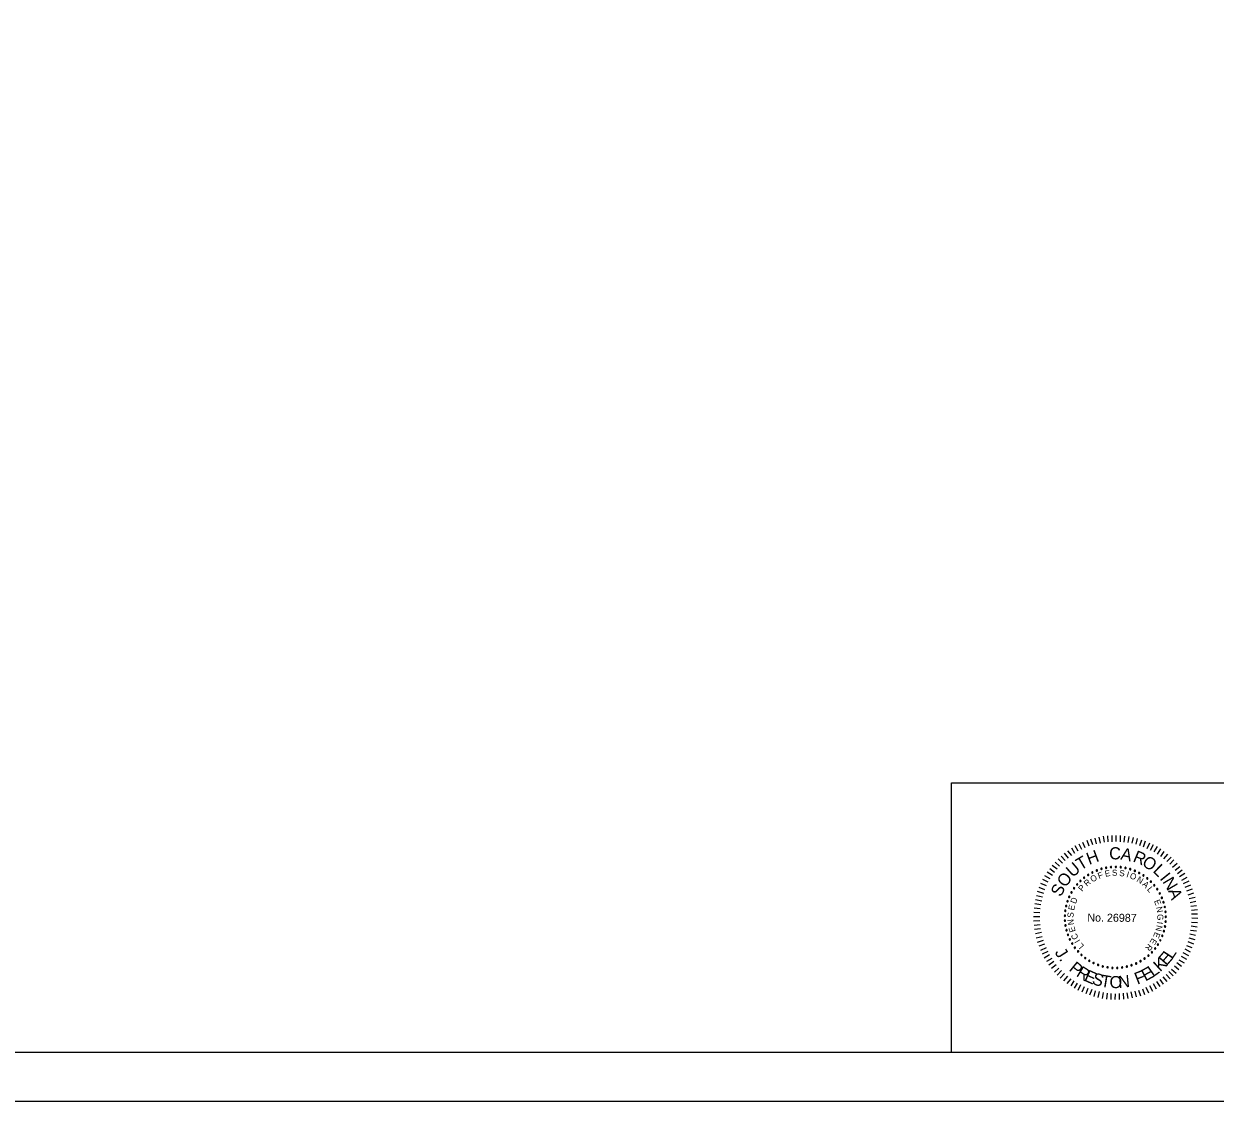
# Model space of a CAD drawing. Extents: x 2799.7 to 2896, y 515.2 to 573.9.
# Drawn here: x 2834.77 to 2867.23, y 515.22 to 544.56 of the extents above; entities that cross this region are included whole.
import ezdxf

# ---------------------------------------------------------------- set-up
doc = ezdxf.new("R2010")
doc.units = 0
for name, color, linetype in [('BR_BORDER LINES', 7, 'Continuous'), ('BR_TEXT', 7, 'Continuous'), ('Level 31', 7, 'Continuous')]:
    doc.layers.add(name, color=color, linetype=linetype)

msp = doc.modelspace()

# ---------------------------------------------------------------- linework, layer by layer
at = {"layer": 'BR_BORDER LINES'}
for p, q in [((2860.05, 523.89), (2874.358, 523.89)), ((2860.05, 516.556), (2860.05, 523.89)), ((2804.582, 516.556), (2894.359, 516.556))]:
    msp.add_line(p, q, dxfattribs=at)
at = {"layer": 'BR_TEXT'}
for p, q in [((2863.694, 522.12), (2863.631, 522.269)), ((2863.798, 522.165), (2863.742, 522.321)), ((2863.903, 522.198), (2863.845, 522.352)), ((2864, 522.225), (2863.964, 522.387)), ((2864.11, 522.251), (2864.072, 522.409)), ((2864.215, 522.271), (2864.191, 522.434)), ((2864.32, 522.282), (2864.31, 522.444)), ((2864.426, 522.288), (2864.427, 522.459)), ((2864.538, 522.293), (2864.539, 522.458)), ((2864.65, 522.286), (2864.656, 522.457)), ((2864.757, 522.278), (2864.77, 522.44)), ((2864.86, 522.266), (2864.889, 522.428)), ((2864.968, 522.244), (2865.006, 522.402)), ((2865.077, 522.216), (2865.12, 522.378)), ((2865.176, 522.188), (2865.234, 522.34)), ((2865.281, 522.152), (2865.339, 522.307)), ((2863.237, 521.84), (2863.13, 521.973)), ((2863.326, 521.908), (2863.222, 522.043)), ((2863.409, 521.964), (2863.328, 522.109)), ((2863.504, 522.027), (2863.422, 522.172)), ((2863.596, 522.075), (2863.526, 522.224)), ((2865.376, 522.106), (2865.451, 522.254)), ((2865.472, 522.059), (2865.556, 522.207)), ((2865.572, 522.01), (2865.658, 522.154)), ((2865.661, 521.946), (2865.751, 522.089)), ((2865.75, 521.888), (2865.847, 522.022)), ((2865.836, 521.818), (2865.945, 521.95)), ((2862.925, 521.536), (2862.793, 521.64)), ((2862.992, 521.62), (2862.876, 521.733)), ((2863.071, 521.701), (2862.953, 521.819)), ((2863.149, 521.774), (2863.038, 521.894)), ((2865.92, 521.751), (2866.036, 521.869)), ((2865.995, 521.677), (2866.111, 521.793)), ((2866.07, 521.594), (2866.197, 521.705)), ((2862.733, 521.272), (2862.59, 521.358)), ((2862.798, 521.37), (2862.654, 521.458)), ((2862.856, 521.447), (2862.724, 521.553)), ((2866.143, 521.509), (2866.267, 521.611)), ((2866.206, 521.419), (2866.337, 521.523)), ((2866.265, 521.341), (2866.405, 521.427)), ((2866.323, 521.242), (2866.466, 521.326)), ((2862.593, 520.98), (2862.438, 521.038)), ((2862.64, 521.083), (2862.487, 521.15)), ((2862.686, 521.181), (2862.536, 521.255)), ((2866.371, 521.15), (2866.525, 521.222)), ((2866.418, 521.051), (2866.57, 521.116)), ((2866.463, 520.948), (2866.614, 521.004)), ((2862.508, 520.665), (2862.342, 520.707)), ((2862.528, 520.777), (2862.365, 520.817)), ((2862.56, 520.873), (2862.396, 520.933)), ((2866.499, 520.84), (2866.652, 520.898)), ((2866.525, 520.744), (2866.686, 520.781)), ((2866.547, 520.631), (2866.708, 520.671)), ((2862.46, 520.354), (2862.288, 520.355)), ((2862.468, 520.459), (2862.303, 520.479)), ((2862.48, 520.569), (2862.318, 520.591)), ((2866.569, 520.535), (2866.727, 520.554)), ((2866.587, 520.425), (2866.749, 520.442)), ((2866.59, 520.32), (2866.751, 520.319)), ((2862.458, 520.13), (2862.286, 520.127)), ((2862.454, 520.244), (2862.287, 520.246)), ((2862.464, 520.027), (2862.299, 520.007)), ((2866.589, 520.096), (2866.749, 520.09)), ((2866.596, 520.21), (2866.759, 520.209)), ((2862.475, 519.917), (2862.312, 519.893)), ((2862.501, 519.811), (2862.334, 519.776)), ((2862.519, 519.699), (2862.356, 519.661)), ((2866.54, 519.778), (2866.7, 519.74)), ((2866.564, 519.883), (2866.722, 519.856)), ((2866.583, 519.993), (2866.746, 519.971)), ((2862.55, 519.6), (2862.385, 519.544)), ((2862.581, 519.497), (2862.425, 519.441)), ((2862.626, 519.398), (2862.472, 519.326)), ((2866.404, 519.367), (2866.555, 519.293)), ((2866.451, 519.465), (2866.601, 519.407)), ((2866.488, 519.568), (2866.641, 519.509)), ((2866.516, 519.666), (2866.676, 519.626)), ((2862.671, 519.302), (2862.519, 519.223)), ((2862.716, 519.203), (2862.571, 519.12)), ((2862.779, 519.104), (2862.634, 519.021)), ((2862.836, 519.026), (2862.702, 518.928)), ((2866.246, 519.075), (2866.385, 518.99)), ((2866.306, 519.173), (2866.448, 519.088)), ((2866.355, 519.271), (2866.508, 519.19)), ((2862.904, 518.936), (2862.77, 518.832)), ((2862.969, 518.846), (2862.852, 518.737)), ((2863.047, 518.777), (2862.927, 518.657)), ((2865.971, 518.753), (2866.084, 518.631)), ((2866.047, 518.821), (2866.172, 518.71)), ((2866.121, 518.909), (2866.244, 518.803)), ((2866.186, 518.998), (2866.316, 518.899)), ((2863.124, 518.696), (2863.011, 518.574)), ((2863.21, 518.627), (2863.101, 518.502)), ((2863.299, 518.557), (2863.192, 518.43)), ((2863.381, 518.499), (2863.297, 518.361)), ((2863.474, 518.439), (2863.39, 518.296)), ((2863.565, 518.386), (2863.493, 518.238)), ((2865.543, 518.422), (2865.626, 518.277)), ((2865.632, 518.481), (2865.721, 518.341)), ((2865.722, 518.537), (2865.817, 518.408)), ((2865.81, 518.605), (2865.916, 518.479)), ((2865.895, 518.673), (2866.008, 518.549)), ((2863.663, 518.339), (2863.598, 518.191)), ((2863.766, 518.293), (2863.707, 518.142)), ((2863.871, 518.26), (2863.81, 518.105)), ((2863.967, 518.227), (2863.929, 518.069)), ((2864.076, 518.208), (2864.036, 518.043)), ((2864.181, 518.177), (2864.155, 518.022)), ((2864.286, 518.165), (2864.274, 518)), ((2864.392, 518.157), (2864.39, 517.992)), ((2864.504, 518.149), (2864.502, 517.987)), ((2864.616, 518.155), (2864.619, 517.99)), ((2864.723, 518.161), (2864.734, 517.996)), ((2864.827, 518.172), (2864.853, 518.016)), ((2864.934, 518.201), (2864.97, 518.036)), ((2865.044, 518.218), (2865.084, 518.06)), ((2865.143, 518.249), (2865.199, 518.093)), ((2865.249, 518.28), (2865.305, 518.129)), ((2865.345, 518.325), (2865.417, 518.176)), ((2865.442, 518.37), (2865.523, 518.221))]:
    msp.add_line(p, q, dxfattribs=at)
for centre, start, end in [((2864.526, 521.6), 359.5268, 179.5268), ((2863.662, 521.306), 38.2961, 218.2961), ((2863.662, 521.306), 218.2961, 38.2961), ((2863.771, 521.383), 32.7576, 212.7576), ((2863.771, 521.383), 212.7576, 32.7576), ((2863.886, 521.449), 27.2191, 207.2191), ((2863.886, 521.449), 207.2191, 27.2191), ((2864.007, 521.504), 21.6807, 201.6807), ((2864.007, 521.504), 201.6807, 21.6807), ((2864.133, 521.547), 16.1422, 196.1422), ((2864.133, 521.547), 196.1422, 16.1422), ((2864.262, 521.577), 10.6038, 190.6038), ((2864.262, 521.577), 190.6038, 10.6038), ((2864.394, 521.595), 5.0653, 185.0653), ((2864.394, 521.595), 185.0653, 5.0653), ((2864.526, 521.6), 179.5268, 359.5268), ((2864.659, 521.593), 173.9884, 353.9884), ((2864.659, 521.593), 353.9884, 173.9884), ((2864.79, 521.572), 348.4499, 168.4499), ((2864.79, 521.572), 168.4499, 348.4499), ((2864.919, 521.539), 162.9114, 342.9114), ((2864.919, 521.539), 342.9114, 162.9114), ((2865.044, 521.493), 157.373, 337.373), ((2865.044, 521.493), 337.373, 157.373), ((2865.164, 521.436), 151.8345, 331.8345), ((2865.164, 521.436), 331.8345, 151.8345), ((2865.278, 521.368), 146.2961, 326.2961), ((2865.278, 521.368), 326.2961, 146.2961), ((2865.384, 521.289), 140.7576, 320.7576), ((2865.384, 521.289), 320.7576, 140.7576), ((2863.389, 521.018), 54.9114, 234.9114), ((2863.389, 521.018), 234.9114, 54.9114), ((2863.47, 521.123), 49.373, 229.373), ((2863.47, 521.123), 229.373, 49.373), ((2863.562, 521.219), 43.8345, 223.8345), ((2863.562, 521.219), 223.8345, 43.8345), ((2865.483, 521.199), 135.2191, 315.2191), ((2865.483, 521.199), 315.2191, 135.2191), ((2865.573, 521.101), 129.6807, 309.6807), ((2865.573, 521.101), 309.6807, 129.6807), ((2865.652, 520.995), 124.1422, 304.1422), ((2865.652, 520.995), 304.1422, 124.1422), ((2863.209, 520.664), 71.5268, 251.5268), ((2863.209, 520.664), 251.5268, 71.5268), ((2863.257, 520.787), 65.9884, 245.9884), ((2863.257, 520.787), 245.9884, 65.9884), ((2863.317, 520.906), 60.4499, 240.4499), ((2863.317, 520.906), 240.4499, 60.4499), ((2865.721, 520.881), 118.6038, 298.6038), ((2865.721, 520.881), 298.6038, 118.6038), ((2865.779, 520.761), 113.0653, 293.0653), ((2865.779, 520.761), 293.0653, 113.0653), ((2865.825, 520.637), 107.5268, 287.5268), ((2865.825, 520.637), 287.5268, 107.5268), ((2863.149, 520.405), 82.6038, 262.6038), ((2863.149, 520.405), 262.6038, 82.6038), ((2863.173, 520.536), 77.0653, 257.0653), ((2863.173, 520.536), 257.0653, 77.0653), ((2865.858, 520.508), 101.9884, 281.9884), ((2865.858, 520.508), 281.9884, 101.9884), ((2865.879, 520.377), 96.4499, 276.4499), ((2865.879, 520.377), 276.4499, 96.4499), ((2863.138, 520.272), 88.1422, 268.1422), ((2863.14, 520.14), 93.6807, 273.6807), ((2863.154, 520.008), 99.2191, 279.2191), ((2863.138, 520.272), 268.1422, 88.1422), ((2863.14, 520.14), 273.6807, 93.6807), ((2863.154, 520.008), 279.2191, 99.2191), ((2865.866, 519.98), 79.8345, 259.8345), ((2865.866, 519.98), 259.8345, 79.8345), ((2865.883, 520.112), 85.373, 265.373), ((2865.887, 520.244), 90.9114, 270.9114), ((2865.883, 520.112), 265.373, 85.373), ((2865.887, 520.244), 270.9114, 90.9114), ((2863.182, 519.878), 104.7576, 284.7576), ((2863.182, 519.878), 284.7576, 104.7576), ((2863.222, 519.751), 110.2961, 290.2961), ((2863.222, 519.751), 290.2961, 110.2961), ((2865.793, 519.724), 68.7576, 248.7576), ((2865.793, 519.724), 248.7576, 68.7576), ((2865.836, 519.85), 74.2961, 254.2961), ((2865.836, 519.85), 254.2961, 74.2961), ((2863.273, 519.628), 115.8345, 295.8345), ((2863.273, 519.628), 295.8345, 115.8345), ((2863.337, 519.512), 121.373, 301.373), ((2863.337, 519.512), 301.373, 121.373), ((2863.411, 519.401), 126.9114, 306.9114), ((2863.411, 519.401), 306.9114, 126.9114), ((2865.597, 519.379), 52.1422, 232.1422), ((2865.597, 519.379), 232.1422, 52.1422), ((2865.673, 519.488), 57.6807, 237.6807), ((2865.673, 519.488), 237.6807, 57.6807), ((2865.739, 519.603), 63.2191, 243.2191), ((2865.739, 519.603), 243.2191, 63.2191), ((2863.496, 519.299), 132.4499, 312.4499), ((2863.496, 519.299), 312.4499, 132.4499), ((2863.59, 519.205), 137.9884, 317.9884), ((2863.59, 519.205), 317.9884, 137.9884), ((2863.693, 519.121), 143.5268, 323.5268), ((2863.693, 519.121), 323.5268, 143.5268), ((2863.803, 519.047), 149.0653, 329.0653), ((2863.803, 519.047), 329.0653, 149.0653), ((2865.197, 519.033), 29.9884, 209.9884), ((2865.197, 519.033), 209.9884, 29.9884), ((2865.309, 519.104), 35.5268, 215.5268), ((2865.309, 519.104), 215.5268, 35.5268), ((2865.414, 519.187), 41.0653, 221.0653), ((2865.414, 519.187), 221.0653, 41.0653), ((2865.51, 519.278), 46.6038, 226.6038), ((2865.51, 519.278), 226.6038, 46.6038), ((2863.92, 518.984), 154.6038, 334.6038), ((2863.92, 518.984), 334.6038, 154.6038), ((2864.043, 518.933), 160.1422, 340.1422), ((2864.043, 518.933), 340.1422, 160.1422), ((2864.17, 518.893), 165.6807, 345.6807), ((2864.17, 518.893), 345.6807, 165.6807), ((2864.3, 518.866), 351.2191, 171.2191), ((2864.3, 518.866), 171.2191, 351.2191), ((2864.432, 518.852), 356.7576, 176.7576), ((2864.432, 518.852), 176.7576, 356.7576), ((2864.565, 518.851), 2.2961, 182.2961), ((2864.565, 518.851), 182.2961, 2.2961), ((2864.697, 518.862), 7.8345, 187.8345), ((2864.697, 518.862), 187.8345, 7.8345), ((2864.828, 518.887), 13.373, 193.373), ((2864.828, 518.887), 193.373, 13.373), ((2864.956, 518.923), 18.9114, 198.9114), ((2864.956, 518.923), 198.9114, 18.9114), ((2865.079, 518.972), 24.4499, 204.4499), ((2865.079, 518.972), 204.4499, 24.4499)]:
    msp.add_arc(centre, 0.0187, start, end, dxfattribs=at)
at = {"layer": 'Level 31'}
msp.add_lwpolyline([(2799.693, 515.223), (2895.694, 515.223), (2895.694, 573.89), (2799.693, 573.89)], close=True, dxfattribs=at)

# ---------------------------------------------------------------- texts
at = {"layer": 'BR_TEXT'}
for s, height, rotation, p in [('H', 0.331, 20.3637, (2863.799, 521.652)), ('C', 0.331, 359.5482, (2864.344, 521.807)), ('A', 0.331, 348.1981, (2864.641, 521.809)), ('R', 0.331, 337.4344, (2864.97, 521.756)), ('U', 0.331, 40.8022, (2863.348, 521.299)), ('T', 0.331, 30.4992, (2863.564, 521.498)), ('O', 0.33, 326.5869, (2865.216, 521.658)), ('L', 0.331, 315.9488, (2865.516, 521.478)), ('O', 0.331, 52.0267, (2863.149, 521.022)), ('O', 0.166, 30.8477, (2863.889, 521.175)), ('F', 0.166, 20.6127, (2864.069, 521.271)), ('E', 0.166, 11.4103, (2864.243, 521.329)), ('S', 0.166, 2.208, (2864.423, 521.358)), ('S', 0.166, 352.6608, (2864.613, 521.357)), ('I', 0.166, 343.1136, (2864.801, 521.325)), ('O', 0.166, 338.4392, (2864.89, 521.298)), ('N', 0.166, 328.2042, (2865.076, 521.214)), ('I', 0.331, 308.6613, (2865.706, 521.28)), ('N', 0.331, 300.7037, (2865.788, 521.201)), ('S', 0.33, 63.2511, (2863.028, 520.767)), ('P', 0.166, 49.9421, (2863.611, 520.917)), ('R', 0.166, 40.3949, (2863.739, 521.058)), ('A', 0.166, 318.657, (2865.233, 521.108)), ('L', 0.166, 309.4546, (2865.366, 520.982)), ('D', 0.166, 69.0364, (2863.433, 520.583)), ('E', 0.166, 291.049, (2865.563, 520.674)), ('A', 0.331, 289.4792, (2865.946, 520.953)), ('S', 0.166, 87.786, (2863.373, 520.216)), ('E', 0.166, 78.2388, (2863.388, 520.406)), ('No. 26987', 0.218, 359.5268, (2863.749, 520.114)), ('N', 0.166, 281.8466, (2865.622, 520.501)), ('N', 0.166, 97.3332, (2863.39, 520.027)), ('N', 0.166, 257.7339, (2865.64, 520.024)), ('I', 0.166, 262.4084, (2865.652, 520.116)), ('G', 0.166, 272.2995, (2865.653, 520.313)), ('E', 0.166, 106.5355, (2863.435, 519.849)), ('C', 0.166, 116.4266, (2863.515, 519.669)), ('E', 0.166, 248.1867, (2865.592, 519.84)), ('J', 0.329, 302.9559, (2862.85, 519.268)), ('I', 0.166, 121.1011, (2863.563, 519.59)), ('L', 0.166, 129.9595, (2863.671, 519.45)), ('R', 0.166, 229.782, (2865.417, 519.52)), ('E', 0.166, 238.9844, (2865.517, 519.673)), ('.', 0.329, 309.3974, (2862.968, 519.087)), ('P', 0.329, 321.1035, (2863.23, 518.795)), ('K', 0.329, 42.3031, (2865.732, 518.729)), ('E', 0.329, 49.3639, (2865.906, 518.89)), ('L', 0.329, 56.4247, (2866.06, 519.07)), ('R', 0.329, 328.5359, (2863.426, 518.64)), ('E', 0.329, 335.9684, (2863.639, 518.512)), ('S', 0.329, 343.0292, (2863.856, 518.417)), ('F', 0.329, 21.1206, (2865.111, 518.392)), ('E', 0.329, 28.1814, (2865.331, 518.479)), ('L', 0.329, 35.2422, (2865.539, 518.591)), ('T', 0.329, 350.4617, (2864.095, 518.346)), ('O', 0.329, 358.1419, (2864.35, 518.306)), ('N', 0.329, 5.8221, (2864.607, 518.301))]:
    msp.add_text(s, height=height, rotation=rotation, dxfattribs=at).set_placement(p)

doc.saveas('drawing.dxf')
